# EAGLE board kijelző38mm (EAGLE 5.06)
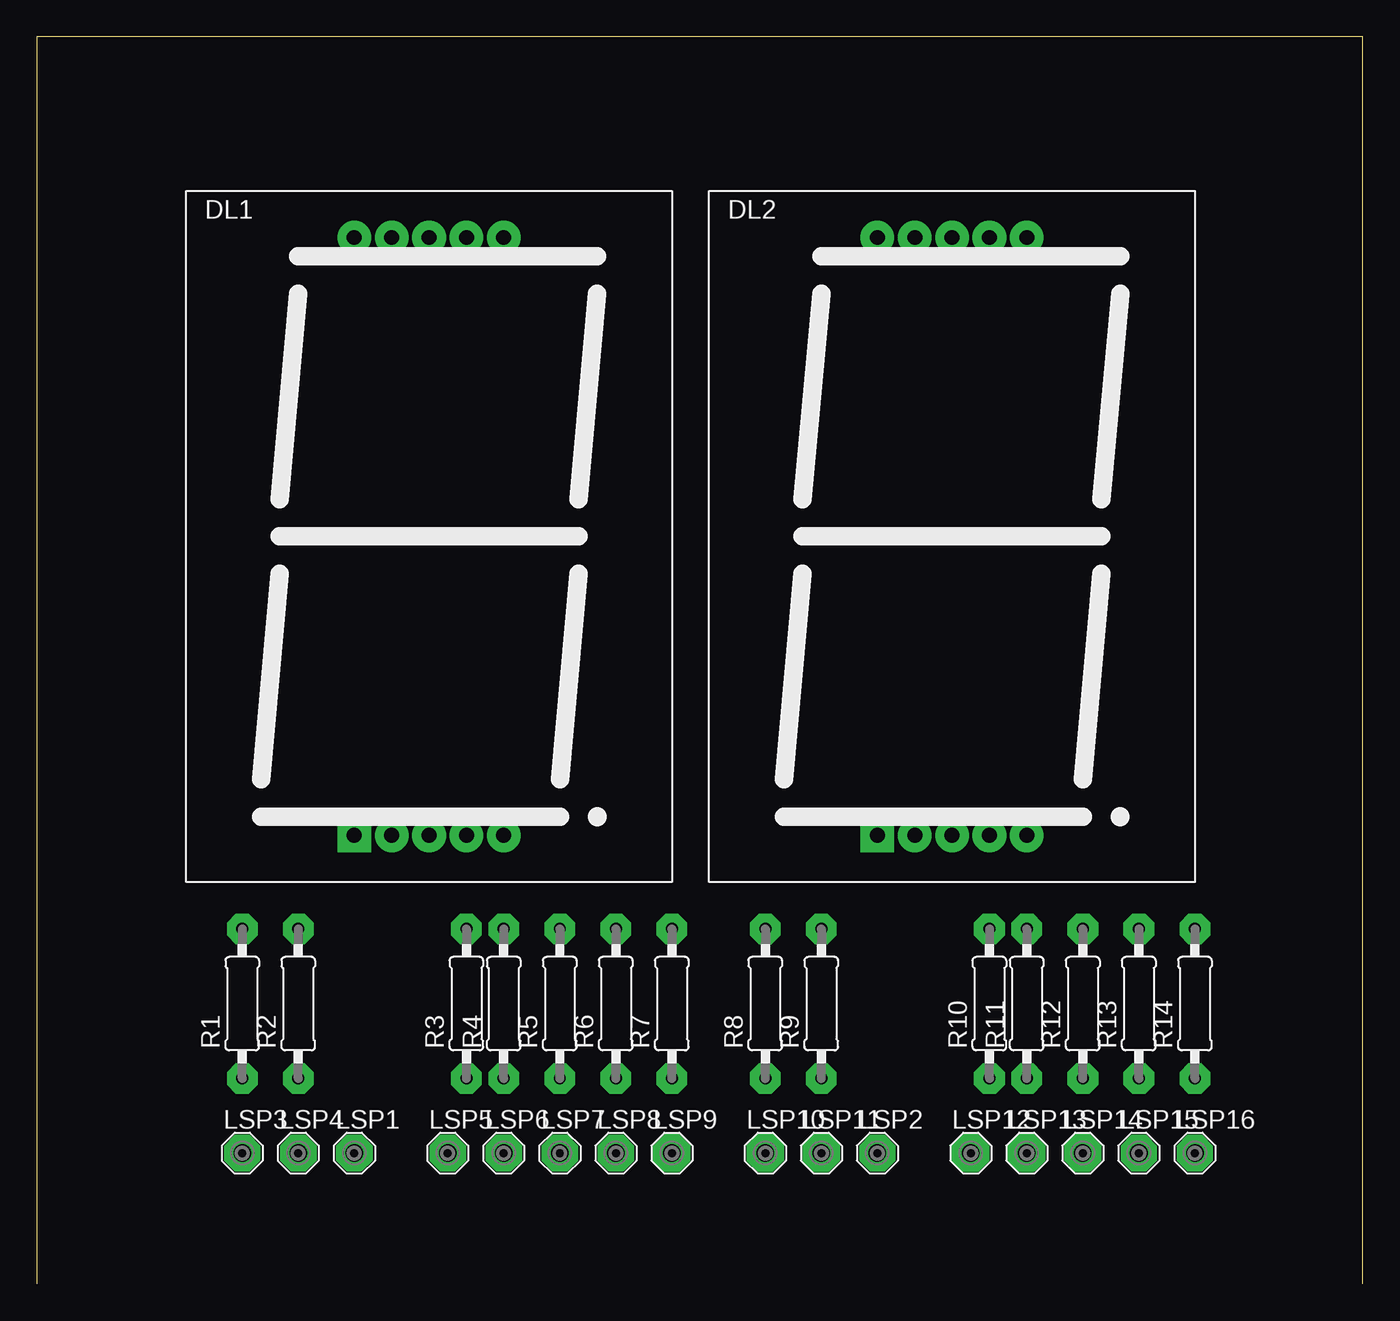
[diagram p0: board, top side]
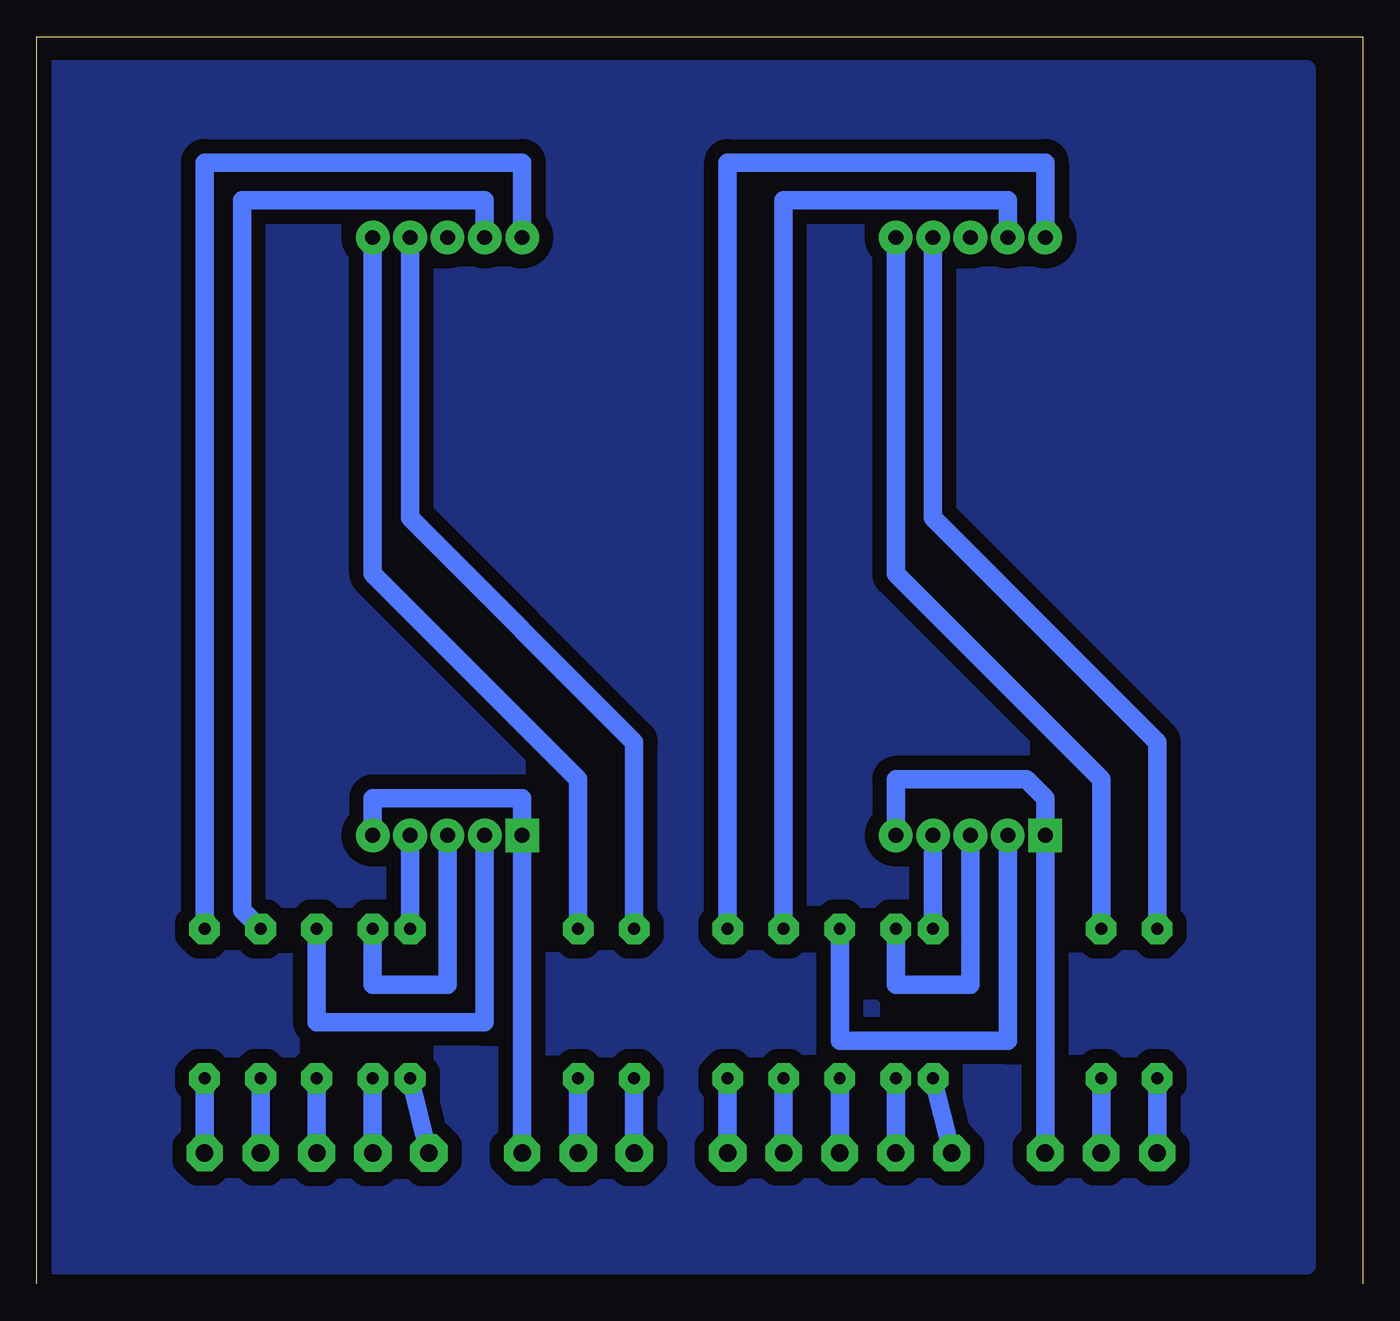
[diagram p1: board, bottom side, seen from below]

Size 90.15 x 84.76 mm. Coordinates in mm from the lower left corner, seen from the top.
Outline: 90.15,0 90.15,84.76 0,84.76 0,0
Copper layers (1*16): Top 0.035mm / dielectric 1.5mm / Bottom 0.035mm
Design rules "default *": minimum track width 10mil, minimum drill 24mil, track to track 38mil, track to pad 38mil, pad to pad 8mil, via to via 8mil, smd to smd 8mil, copper to edge 40mil, drill to drill 8mil, minimum pad ring 25mil, minimum via ring 8mil, stop-mask expansion 4mil, vias tented up to drill 0mil, thermal gap 10mil

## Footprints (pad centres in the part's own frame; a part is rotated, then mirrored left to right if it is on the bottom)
SA15-11 = drill 1.016 square: 1 -5.08,-20.32 | drill 1.016 round: 2 -2.54,-20.32; 3 0,-20.32; 4 2.54,-20.32; 5 5.08,-20.32; 6 5.08,20.32; 7 2.54,20.32; 8 0,20.32; 9 -2.54,20.32; 10 -5.08,20.32
MCS08 = drill 1.194 pad 2.159 octagon: MP 0,0
0207/10 = drill 0.813 octagon: 1 -5.08,0; 2 5.08,0

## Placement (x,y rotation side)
DL1  SA15-11*  [SA15-11]  26.67,50.8 0 top
DL2  SA15-11*  [SA15-11]  62.23,50.8 0 top
LSP1  MCS08  [MCS08]  21.59,8.89 0 top
LSP2  MCS08  [MCS08]  57.15,8.89 0 top
LSP3  MCS08  [MCS08]  13.97,8.89 0 top
LSP4  MCS08  [MCS08]  17.78,8.89 0 top
LSP5  MCS08  [MCS08]  27.94,8.89 0 top
LSP6  MCS08  [MCS08]  31.75,8.89 0 top
LSP7  MCS08  [MCS08]  35.56,8.89 0 top
LSP8  MCS08  [MCS08]  39.37,8.89 0 top
LSP9  MCS08  [MCS08]  43.18,8.89 0 top
LSP10  MCS08  [MCS08]  49.53,8.89 0 top
LSP11  MCS08  [MCS08]  53.34,8.89 0 top
LSP12  MCS08  [MCS08]  63.5,8.89 0 top
LSP13  MCS08  [MCS08]  67.31,8.89 0 top
LSP14  MCS08  [MCS08]  71.12,8.89 0 top
LSP15  MCS08  [MCS08]  74.93,8.89 0 top
LSP16  MCS08  [MCS08]  78.74,8.89 0 top
R1  [0207/10]  13.97,19.05 90 top
R2  [0207/10]  17.78,19.05 90 top
R3  [0207/10]  29.21,19.05 90 top
R4  [0207/10]  31.75,19.05 90 top
R5  [0207/10]  35.56,19.05 90 top
R6  [0207/10]  39.37,19.05 90 top
R7  [0207/10]  43.18,19.05 90 top
R8  [0207/10]  49.53,19.05 90 top
R9  [0207/10]  53.34,19.05 90 top
R10  [0207/10]  64.77,19.05 90 top
R11  [0207/10]  67.31,19.05 90 top
R12  [0207/10]  71.12,19.05 90 top
R13  [0207/10]  74.93,19.05 90 top
R14  [0207/10]  78.74,19.05 90 top

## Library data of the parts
DL1 DL2 = kingbright
LSP1-LSP16 = solpad
R1-R14 = rcl

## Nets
N$1: DL1.7 R1.2
N$2: DL1.6 R2.2
N$3: DL1.4 R3.2
N$4: DL1.3 R4.2
N$5: DL1.2 R5.2
N$6: DL1.9 R6.2
N$7: DL1.10 R7.2
N$8: DL2.7 R8.2
N$9: DL2.6 R9.2
N$10: DL2.4 R10.2
N$11: DL2.3 R11.2
N$12: DL2.9 R13.2
N$13: DL2.2 R12.2
N$14: DL2.10 R14.2
N$15: DL2.8
N$16: DL2.1 DL2.5 LSP2.MP
N$18: DL1.8
N$19: DL1.1 DL1.5 LSP1.MP
N$21: LSP3.MP R1.1
N$22: LSP4.MP R2.1
N$23: LSP5.MP R3.1
N$24: LSP6.MP R4.1
N$25: LSP7.MP R5.1
N$26: LSP8.MP R6.1
N$27: LSP9.MP R7.1
N$28: LSP10.MP R8.1
N$29: LSP11.MP R9.1
N$30: LSP12.MP R10.1
N$31: LSP13.MP R11.1
N$32: LSP14.MP R12.1
N$33: LSP15.MP R13.1
N$34: LSP16.MP R14.1

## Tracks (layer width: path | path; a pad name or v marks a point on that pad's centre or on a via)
N$1
  Bottom 1.27: R1.2 13.97,36.83 29.21,52.07 DL1.7
N$2
  Bottom 1.27: R2.2 17.78,34.29 31.75,48.26 DL1.6
N$3
  Bottom 0.254: 29.21,29.21 DL1.4
  Bottom 1.27: R3.2 29.21,29.21
N$4
  Bottom 1.27: DL1.3 26.67,20.32 31.75,20.32 R4.2
N$5
  Bottom 1.27: DL1.2 24.13,16.51 35.56,16.51 R5.2
N$6
  Bottom 1.27: R6.2 39.37,73.66 24.13,73.66 DL1.9
N$7
  Bottom 1.27: R7.2 43.18,76.2 21.59,76.2 DL1.10
N$8
  Bottom 1.27: DL2.7 64.77,52.07 49.53,36.83 R8.2
N$9
  Bottom 1.27: DL2.6 67.31,48.26 53.34,34.29 R9.2
N$10
  Bottom 1.27: R10.2 DL2.4
N$11
  Bottom 1.27: R11.2 67.31,20.32 62.23,20.32 DL2.3
N$12
  Bottom 1.27: DL2.9 59.69,73.66 76.2,73.66 76.2,25.4 R13.2
N$13
  Bottom 1.27: DL2.2 59.69,17.78 71.12,17.78 R12.2
N$14
  Bottom 1.27: DL2.10 57.15,76.2 78.74,76.2 R14.2
N$16
  Bottom 1.27: LSP2.MP DL2.1 57.15,33.02 67.31,33.02 DL2.5
N$17
  pour Bottom: 88.9,82.55 3.81,82.55 3.81,1.27 88.9,1.27
N$19
  Bottom 1.27: DL1.5 31.75,34.29 22.86,34.29 21.59,33.02 DL1.1 LSP1.MP
N$21
  Bottom 1.27: LSP3.MP R1.1
N$22
  Bottom 1.27: LSP4.MP R2.1
N$23
  Bottom 1.27: LSP5.MP R3.1
N$24
  Bottom 1.27: LSP6.MP R4.1
N$25
  Bottom 1.27: LSP7.MP R5.1
N$26
  Bottom 1.27: LSP8.MP R6.1
N$27
  Bottom 1.27: LSP9.MP R7.1
N$28
  Bottom 1.27: LSP10.MP R8.1
N$29
  Bottom 1.27: LSP11.MP R9.1
N$30
  Bottom 1.27: LSP12.MP R10.1
N$31
  Bottom 1.27: LSP13.MP R11.1
N$32
  Bottom 1.27: LSP14.MP R12.1
N$33
  Bottom 1.27: LSP15.MP R13.1
N$34
  Bottom 1.27: LSP16.MP R14.1
N$35  (via drill 0.6 pad 3.81)
  other vias: -31.75,-27.94
N$41  (via drill 0.6 pad 2.54)
  other vias: 43.18,8.89
N$42  (via drill 0.6 pad 2.54)
  other vias: 49.53,8.89
N$43  (via drill 0.6 pad 2.54)
  other vias: 53.34,8.89
N$44  (via drill 0.6 pad 2.54)
  other vias: 63.5,8.89
N$45  (via drill 0.6 pad 2.54)
  other vias: 67.31,8.89
N$46  (via drill 0.6 pad 2.54)
  other vias: 71.12,8.89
